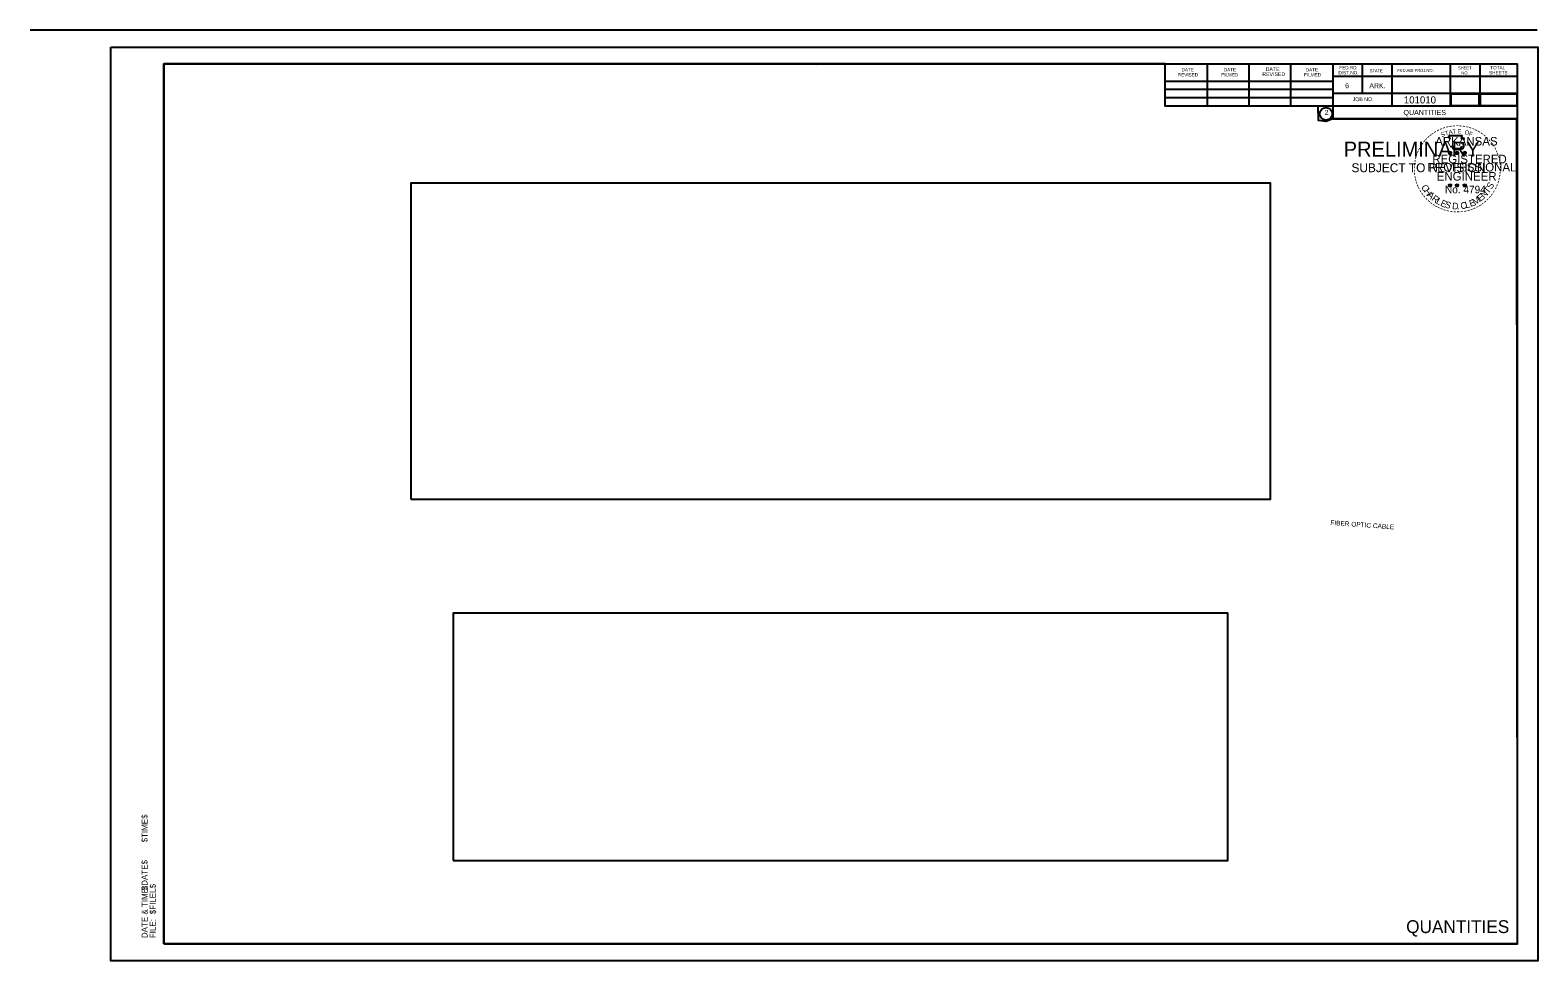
# Model space of a CAD drawing. Extents: x 9844 to 18514, y 8651 to 12569.
# Drawn here: x 9844 to 11605, y 9980 to 11067 of the extents above; entities that cross this region are included whole.
import ezdxf

# ---------------------------------------------------------------- set-up
doc = ezdxf.new("R2010")
doc.units = 0
for name, color, linetype in [('Default', 7, 'Continuous'), ('Quantities', 7, 'Continuous'), ('R_Border Notes', 7, 'Continuous'), ('R_No Plot', 7, 'Continuous'), ('S_FIBER_OPTIC_CABLE_ANNOT', 7, 'Continuous'), ('STAMP_PE_CRAFTON-SIGNATURE', 7, 'Continuous'), ('STAMP_PE_SEAL-INFO', 7, 'Continuous'), ('STAMP_PE_TXT', 7, 'Continuous'), ('STAMP_PRELIMINARY', 7, 'Continuous'), ('Total_Pages', 7, 'Continuous')]:
    doc.layers.add(name, color=color, linetype=linetype)

msp = doc.modelspace()

# ---------------------------------------------------------------- linework, layer by layer
at = {"layer": 'Quantities'}
for points in [[(10288.4, 10519), (11292.5, 10519), (11292.5, 10888.2), (10288.4, 10888.2)], [(10338.1, 10097.4), (11242.8, 10097.4), (11242.8, 10386), (10338.1, 10386)]]:
    msp.add_lwpolyline(points, close=True, dxfattribs=at)
at = {"layer": 'R_No Plot'}
msp.add_lwpolyline([(11502.9, 10978.6), (11536.2, 10978.6), (11536.2, 10991.9), (11502.9, 10991.9)], close=True, dxfattribs=at)
at = {"layer": 'STAMP_PE_SEAL-INFO'}
for points in [[(9938, 11046.8), (11604.7, 11046.8), (11604.7, 9980.1), (9938, 9980.1)], [(10000, 10000), (11580.9, 10000), (11580.3, 10963.3), (11365.4, 10963.3), (11357.3, 10959.9), (11348.5, 10961.4), (11348.3, 10977.9), (11169.6, 10977.9), (11169.6, 11027.3), (10000, 11027.3)], [(10000, 10000), (11580.9, 10000), (11580.3, 10963.3), (11365.4, 10963.3), (11357.3, 10959.9), (11348.5, 10961.4), (11348.3, 10977.9), (11169.6, 10977.9), (11169.6, 11027.3), (10000, 11027.3)], [(10000, 10000), (11580.9, 10000), (11580.3, 10963.3), (11365.4, 10963.3), (11357.3, 10959.9), (11348.5, 10961.4), (11348.3, 10977.9), (11169.6, 10977.9), (11169.6, 11027.3), (10000, 11027.3)]]:
    msp.add_lwpolyline(points, close=True, dxfattribs=at)
at = {"layer": 'STAMP_PE_TXT'}
for p, q in [((11500.3, 10924), (11502.1, 10923.5)), ((11500.3, 10924), (11501.6, 10923.8)), ((11500.3, 10924), (11501.5, 10923.4)), ((11501, 10922), (11502.1, 10923.5)), ((11501, 10922), (11501.6, 10923.2)), ((11501, 10922), (11502, 10923.1)), ((11502.1, 10925.3), (11501.8, 10924.1)), ((11503.1, 10922), (11502, 10923.1)), ((11502.1, 10923.5), (11502.1, 10925.3)), ((11502.1, 10925.3), (11502.3, 10924.1)), ((11503.8, 10924), (11502.1, 10923.5)), ((11503.1, 10922), (11502.1, 10923.5)), ((11503.8, 10924), (11502.4, 10923.8)), ((11503.1, 10922), (11502.4, 10923.5)), ((11503.8, 10924), (11502.8, 10923.5)), ((11508.7, 10924), (11510.4, 10923.5)), ((11508.7, 10924), (11509.9, 10923.8)), ((11508.7, 10924), (11509.8, 10923.4)), ((11509.3, 10922), (11510.4, 10923.5)), ((11509.3, 10922), (11510, 10923.2)), ((11509.3, 10922), (11510.4, 10923.1)), ((11510.4, 10925.3), (11510.2, 10924.1)), ((11510.4, 10923.5), (11510.4, 10925.3)), ((11510.4, 10925.3), (11510.6, 10924.1)), ((11512.1, 10924), (11510.4, 10923.5)), ((11511.5, 10922), (11510.4, 10923.5)), ((11511.5, 10922), (11510.4, 10923.1)), ((11512.1, 10924), (11510.7, 10923.8)), ((11511.5, 10922), (11510.8, 10923.5)), ((11512.1, 10924), (11511.1, 10923.5)), ((11517.5, 10924), (11519.2, 10923.4)), ((11517.5, 10924), (11518.7, 10923.8)), ((11517.5, 10924), (11518.7, 10923.4)), ((11518.1, 10921.9), (11519.2, 10923.4)), ((11518.1, 10921.9), (11518.8, 10923.2)), ((11518.1, 10921.9), (11519.2, 10923)), ((11519.2, 10925.3), (11519, 10924)), ((11519.2, 10923.4), (11519.2, 10925.3)), ((11519.2, 10925.3), (11519.5, 10924)), ((11521, 10924), (11519.2, 10923.4)), ((11520.3, 10921.9), (11519.2, 10923.4)), ((11520.3, 10921.9), (11519.2, 10923)), ((11521, 10924), (11519.5, 10923.7)), ((11520.3, 10921.9), (11519.6, 10923.4)), ((11521, 10924), (11519.9, 10923.5)), ((11500.3, 10886.2), (11502, 10885.6)), ((11500.3, 10886.2), (11501.6, 10886)), ((11500.3, 10886.2), (11501.5, 10885.6)), ((11501, 10884.1), (11502, 10885.6)), ((11501, 10884.1), (11501.6, 10885.4)), ((11501, 10884.1), (11502, 10885.2)), ((11502, 10887.4), (11501.8, 10886.2)), ((11502, 10885.6), (11502, 10887.4)), ((11502, 10887.4), (11502.3, 10886.2)), ((11503.8, 10886.2), (11502, 10885.6)), ((11503.1, 10884.1), (11502, 10885.6)), ((11503.1, 10884.1), (11502, 10885.2)), ((11503.8, 10886.2), (11502.3, 10885.9)), ((11503.1, 10884.1), (11502.4, 10885.6)), ((11503.8, 10886.2), (11502.7, 10885.7)), ((11508.6, 10886.2), (11510.4, 10885.6)), ((11508.6, 10886.2), (11509.9, 10886)), ((11508.6, 10886.2), (11509.8, 10885.6)), ((11509.3, 10884.1), (11510.4, 10885.6)), ((11509.3, 10884.1), (11509.9, 10885.4)), ((11509.3, 10884.1), (11510.4, 10885.2)), ((11510.4, 10887.4), (11510.2, 10886.2)), ((11510.4, 10885.6), (11510.4, 10887.4)), ((11510.4, 10887.4), (11510.6, 10886.2)), ((11512.1, 10886.2), (11510.4, 10885.6)), ((11511.4, 10884.1), (11510.4, 10885.6)), ((11511.4, 10884.1), (11510.4, 10885.2)), ((11512.1, 10886.2), (11510.7, 10885.9)), ((11511.4, 10884.1), (11510.8, 10885.6)), ((11512.1, 10886.2), (11511.1, 10885.7)), ((11517.5, 10886.1), (11519.2, 10885.6)), ((11517.5, 10886.1), (11518.7, 10885.9)), ((11517.5, 10886.1), (11518.7, 10885.5)), ((11518.1, 10884.1), (11519.2, 10885.6)), ((11518.1, 10884.1), (11518.8, 10885.3)), ((11518.1, 10884.1), (11519.2, 10885.2)), ((11519.2, 10887.4), (11519, 10886.1)), ((11519.2, 10885.6), (11519.2, 10887.4)), ((11519.2, 10887.4), (11519.5, 10886.1)), ((11520.9, 10886.1), (11519.2, 10885.6)), ((11520.3, 10884.1), (11519.2, 10885.6)), ((11520.3, 10884.1), (11519.2, 10885.2)), ((11520.9, 10886.1), (11519.5, 10885.9)), ((11520.3, 10884.1), (11519.6, 10885.5)), ((11520.9, 10886.1), (11519.9, 10885.6))]:
    msp.add_line(p, q, dxfattribs=at)
for points in [[(11500.5, 10943.4), (11501.9, 10939.3)], [(11518.1, 10938.8), (11518.8, 10940.2), (11515.4, 10940.1), (11516.1, 10943.4), (11500.5, 10943.4)], [(11502.1, 10925.3), (11503.1, 10922), (11500.3, 10924), (11503.8, 10924), (11501, 10922), (11502.1, 10925.3)], [(11503, 10931.3), (11503, 10930.9), (11505.8, 10930.8), (11505.5, 10928.4), (11514.9, 10928.4), (11515.9, 10931.1)], [(11510.4, 10925.3), (11511.5, 10922), (11508.7, 10924), (11512.1, 10924), (11509.3, 10922), (11510.4, 10925.3)], [(11519.2, 10925.3), (11520.3, 10921.9), (11517.5, 10924), (11521, 10924), (11518.1, 10921.9), (11519.2, 10925.3)], [(11502, 10887.4), (11503.1, 10884.1), (11500.3, 10886.2), (11503.8, 10886.2), (11501, 10884.1), (11502, 10887.4)], [(11510.4, 10887.4), (11511.4, 10884.1), (11508.6, 10886.2), (11512.1, 10886.2), (11509.3, 10884.1), (11510.4, 10887.4)], [(11519.2, 10887.4), (11520.3, 10884.1), (11517.5, 10886.1), (11520.9, 10886.1), (11518.1, 10884.1), (11519.2, 10887.4)]]:
    msp.add_lwpolyline(points, dxfattribs=at)
for centre, radius in [((11502, 10923.5), 0.861), ((11502, 10923.5), 0.723), ((11502, 10923.5), 0.579), ((11502, 10923.5), 0.495), ((11502, 10923.5), 0.374), ((11502, 10923.5), 0.248), ((11502, 10923.5), 0.148), ((11510.4, 10923.5), 0.861), ((11510.4, 10923.5), 0.723), ((11510.4, 10923.5), 0.579), ((11510.4, 10923.5), 0.495), ((11510.4, 10923.5), 0.374), ((11510.4, 10923.5), 0.248), ((11510.4, 10923.5), 0.148), ((11519.2, 10923.4), 0.861), ((11519.2, 10923.4), 0.723), ((11519.2, 10923.4), 0.579), ((11519.2, 10923.4), 0.495), ((11519.2, 10923.4), 0.374), ((11519.2, 10923.4), 0.248), ((11519.2, 10923.4), 0.148), ((11502, 10885.6), 0.861), ((11502, 10885.6), 0.723), ((11502, 10885.6), 0.579), ((11502, 10885.6), 0.495), ((11502, 10885.6), 0.374), ((11502, 10885.6), 0.248), ((11502, 10885.6), 0.148), ((11510.4, 10885.6), 0.861), ((11510.4, 10885.6), 0.723), ((11510.4, 10885.6), 0.579), ((11510.4, 10885.6), 0.495), ((11510.4, 10885.6), 0.374), ((11510.4, 10885.6), 0.248), ((11510.4, 10885.6), 0.148), ((11519.2, 10885.6), 0.861), ((11519.2, 10885.6), 0.723), ((11519.2, 10885.6), 0.579), ((11519.2, 10885.6), 0.495), ((11519.2, 10885.6), 0.374), ((11519.2, 10885.6), 0.248), ((11519.2, 10885.6), 0.148)]:
    msp.add_circle(centre, radius, dxfattribs=at)
at = {"layer": 'STAMP_PRELIMINARY'}
for p, q in [((11603.9, 11066.7), (9843.9, 11066.7)), ((10000, 11027.3), (11580.9, 11027.3)), ((10000, 10000), (10000, 11027.3)), ((10762.6, 11026), (10762.6, 11026)), ((10762.6, 11026), (10762.6, 11026)), ((11169.6, 10977.9), (11169.6, 11027.3)), ((11218.9, 10977.9), (11218.9, 11026.3)), ((11267.7, 10977.9), (11267.7, 11026.3)), ((11316.1, 10977.9), (11316.1, 11026.3)), ((11365.4, 11027.3), (11365.4, 10963.3)), ((11399.6, 11027.3), (11399.6, 10992.6)), ((11434.3, 11027.3), (11434.3, 10977.9)), ((11502.2, 11027.3), (11502.2, 10977.9)), ((11536.9, 11027.3), (11536.9, 10977.9)), ((11580.9, 10000), (11580.9, 11027.3)), ((11169.6, 11007.2), (11365.4, 11007.2)), ((11580.9, 11012.6), (11365.4, 11012.6)), ((11580.9, 11012.7), (11580.9, 11012.7)), ((11169.6, 10997.9), (11365.4, 10997.9)), ((11169.6, 10988.2), (11365.4, 10988.2)), ((11580.9, 10992.6), (11365.4, 10992.6)), ((11580.9, 10977.9), (11169.6, 10977.9)), ((11365.4, 10963.3), (11580.9, 10963.3)), ((11580.9, 10000), (10000, 10000))]:
    msp.add_line(p, q, dxfattribs=at)
msp.add_circle((11357.3, 10969), 7.33, dxfattribs=at)
at = {"layer": 'Total_Pages'}
msp.add_lwpolyline([(11537.4, 10978.6), (11580.4, 10978.6), (11580.4, 10991.9), (11537.4, 10991.9)], close=True, dxfattribs=at)

# ---------------------------------------------------------------- texts
at = {"layer": 'Default'}
for s, height, p in [('$TIME$', 6.98, (9981, 10118.4)), ('$DATE$', 6.98, (9981, 10062.5)), ('DATE & TIME:', 6.984, (9981, 10006.6)), ('$FILEL$', 6.98, (9990.6, 10034.5)), ('FILE: ', 6.98, (9990.6, 10006.6))]:
    msp.add_text(s, height=height, rotation=90, dxfattribs=at).set_placement(p)
at = {"layer": 'R_Border Notes'}
for s, height, p in [('101010', 8.4, (11448.2, 10981.1)), ('QUANTITIES', 6, (11447.7, 10967.6))]:
    msp.add_text(s, height=height, dxfattribs=at).set_placement(p)
at = {"layer": 'S_FIBER_OPTIC_CABLE_ANNOT'}
msp.add_text('FIBER OPTIC CABLE', height=5.5, rotation=356.029, dxfattribs=at).set_placement((11362.2, 10489))
at = {"layer": 'STAMP_PE_CRAFTON-SIGNATURE'}
for s, height, p in [('PRELIMINARY', 17.5, (11377.9, 10919)), ('SUBJECT TO REVISION', 10.376, (11387, 10900.9))]:
    msp.add_text(s, height=height, dxfattribs=at).set_placement(p)
at = {"layer": 'STAMP_PE_TXT'}
for s, height, rotation, p in [('-', 8, 24.3072, (11491.1, 10947.7)), ('-', 8, 19.1761, (11494.3, 10949.1)), ('-', 8, 13.6302, (11498, 10950.3)), ('-', 8, 10.2193, (11501.4, 10951.1)), ('-', 8, 5.8968, (11505, 10951.6)), ('-', 8, 0.1862, (11508.9, 10952)), ('-', 8, 357.743, (11512.5, 10951.9)), ('-', 8, 352.1617, (11516.2, 10951.6)), ('-', 8, 347.2049, (11519.8, 10951.1)), ('-', 8, 342.3362, (11523, 10950.3)), ('-', 8, 337.8551, (11526.7, 10949.2)), ('-', 8, 54.2325, (11471.2, 10930.7)), ('-', 8, 50.6142, (11473.2, 10933.5)), ('-', 8, 48.4231, (11475.3, 10935.9)), ('-', 8, 42.9622, (11477.5, 10938.3)), ('-', 8, 38.9507, (11479.7, 10940.4)), ('-', 8, 36.2317, (11482, 10942.3)), ('-', 8, 34.0636, (11484.9, 10944.3)), ('-', 8, 28.7918, (11487.9, 10946.1)), ('S', 5, 21.594, (11492.3, 10941.8)), ('T', 5, 16.4036, (11496.9, 10943.5)), ('A', 5, 11.2132, (11501, 10944.7)), ('T', 5, 6.0228, (11505.2, 10945.6)), ('E', 5, 0.8323, (11510.8, 10946.1)), ('O', 5, 350.4515, (11518.8, 10945.1)), ('F', 5, 340.0707, (11523.5, 10943.9)), ('-', 8, 334.1211, (11529.8, 10947.8)), ('-', 8, 329.6409, (11532.7, 10946.4)), ('-', 8, 325.8627, (11535.9, 10944.6)), ('-', 8, 320.5297, (11539, 10942.5)), ('-', 8, 315.5786, (11542, 10940)), ('-', 8, 309.8797, (11544.8, 10937.3)), ('-', 8, 306.6522, (11547.5, 10934.3)), ('-', 8, 75.461, (11464.6, 10915.2)), ('-', 8, 72.3945, (11465.6, 10918.8)), ('-', 8, 67.7743, (11466.7, 10921.9)), ('-', 8, 62.8713, (11468, 10925)), ('-', 8, 58.0706, (11469.6, 10928)), ('-', 7, 303.6753, (11549.9, 10931.4)), ('-', 8, 299.6684, (11551.5, 10928.4)), ('-', 8, 294.6628, (11553.1, 10925.3)), ('-', 8, 290.5728, (11554.4, 10922.5)), ('-', 8, 285.1233, (11555.6, 10919.6)), ('-', 8, 89.0622, (11463.4, 10904.7)), ('-', 8, 94.1959, (11463.6, 10901.1)), ('-', 8, 98.9479, (11464, 10897.7)), ('-', 8, 85.1863, (11463.6, 10908.2)), ('-', 8, 81.2013, (11464, 10911.6)), ('-', 8, 280.5493, (11556.6, 10915.9)), ('-', 8, 276.5962, (11557.4, 10912)), ('-', 8, 263.5172, (11557.7, 10901.9)), ('-', 8, 274.3301, (11557.7, 10908.4)), ('-', 8, 269.9407, (11557.8, 10905.2)), ('-', 8, 101.7149, (11464.7, 10894.1)), ('-', 8, 105.4578, (11465.5, 10891.1)), ('-', 8, 109.0874, (11466.5, 10887.9)), ('-', 8, 114.0643, (11467.8, 10884.9)), ('-', 8, 115.7289, (11469.3, 10881.9)), ('C', 7.7, 296.9133, (11468.2, 10883.9)), ('H', 7.7, 303.2799, (11471.1, 10878.7)), ('T', 7.7, 51.5114, (11546.8, 10875.1)), ('S', 7.7, 57.878, (11550.5, 10880.3)), ('-', 8, 244.6197, (11553.5, 10885.1)), ('-', 8, 247.8887, (11554.8, 10888.3)), ('-', 8, 255.7626, (11555.9, 10891.8)), ('-', 8, 255.7626, (11556.8, 10895.3)), ('-', 8, 260.9953, (11557.4, 10898.6)), ('-', 8, 120.4471, (11471.1, 10878.9)), ('-', 8, 125.8934, (11473.1, 10876.1)), ('-', 8, 130.7181, (11475.4, 10873.4)), ('-', 8, 134.2238, (11478, 10870.6)), ('A', 7.7, 316.013, (11474.8, 10873.6)), ('-', 8, 138.9338, (11480.7, 10868.3)), ('-', 8, 144.6463, (11483.4, 10866.3)), ('R', 7.7, 322.3796, (11479.9, 10868.7)), ('L', 7.7, 328.7461, (11485, 10864.9)), ('E', 7.7, 335.1127, (11490.1, 10862.1)), ('S', 7.7, 341.4792, (11495.4, 10860)), ('D', 7.7, 354.2124, (11504.2, 10857.9)), ('C', 7.7, 6.9455, (11514.7, 10857.7)), ('L', 7.7, 13.3121, (11520.6, 10858.7)), ('E', 7.7, 19.6786, (11526.1, 10860.3)), ('M', 7.7, 32.4117, (11531.2, 10862.1)), ('E', 7.7, 38.7783, (11537.6, 10866.2)), ('N', 7.7, 45.1449, (11542, 10869.9)), ('-', 8, 215.7363, (11539.6, 10867.6)), ('-', 8, 221.0851, (11542.4, 10869.9)), ('-', 8, 225.7653, (11545, 10872.5)), ('-', 8, 231.2538, (11547.4, 10875.3)), ('-', 8, 233.8452, (11549.5, 10878.1)), ('-', 8, 239.0712, (11551.5, 10881.4)), ('-', 8, 148.0898, (11486.2, 10864.4)), ('-', 8, 151.5704, (11489.1, 10862.8)), ('-', 8, 154.6002, (11491.7, 10861.6)), ('-', 8, 158.5612, (11494.9, 10860.3)), ('-', 8, 162.7983, (11498.3, 10859.2)), ('-', 8, 167.5555, (11501.9, 10858.4)), ('-', 8, 173.1155, (11505.7, 10857.9)), ('-', 8, 176.5183, (11509.5, 10857.6)), ('-', 8, 181.5918, (11513.2, 10857.7)), ('.', 7.7, 0.5789, (11510.1, 10857.5)), ('-', 8, 185.8167, (11517.2, 10858.1)), ('-', 8, 191.2858, (11520.9, 10858.7)), ('-', 8, 195.4743, (11524.6, 10859.7)), ('-', 8, 200.7184, (11528, 10860.9)), ('-', 8, 204.2516, (11531, 10862.3)), ('-', 8, 207.3568, (11534.2, 10863.9)), ('-', 8, 212.2491, (11537, 10865.6))]:
    msp.add_text(s, height=height, rotation=rotation, dxfattribs=at).set_placement(p)
for s, height, p in [('ARKANSAS', 10, (11484.8, 10932)), ('REGISTERED', 10, (11481.4, 10911.2)), ('PROFESSIONAL', 10, (11475.6, 10901.7)), ('ENGINEER', 10, (11486.6, 10891.1)), ('No. 4794', 8.78, (11496.2, 10876.3))]:
    msp.add_text(s, height=height, dxfattribs=at).set_placement(p)
at = {"layer": 'STAMP_PRELIMINARY'}
for s, height, p in [('DATE', 3.91, (11188.6, 11018.5)), ('DATE', 3.91, (11237.9, 11018.5)), ('DATE', 4.4, (11286.8, 11019)), ('DATE', 3.91, (11333.7, 11018.5)), ('FED.RD.', 3.91, (11372.8, 11020.9)), ('SHEET', 3.42, (11511.5, 11020.9)), ('TOTAL', 3.91, (11549.1, 11020.9)), ('REVISED', 3.91, (11184.2, 11012.6)), ('FILMED', 3.91, (11235, 11012.6)), ('REVISED', 4.4, (11282.9, 11013.1)), ('FILMED', 3.91, (11331.7, 11012.6)), ('DIST.NO.', 3.91, (11371.8, 11015)), ('6', 5.86, (11379.6, 10998.9)), ('STATE', 3.42, (11408.4, 11017.5)), ('FED.AID PROJ.NO.', 3.42, (11440.7, 11018)), ('NO.', 3.42, (11515.4, 11015)), ('SHEETS', 3.91, (11547.7, 11015)), ('JOB NO.', 4.4, (11388.4, 10983.8)), ('ARK.', 5.86, (11407.9, 10998.9)), ('2', 5.86, (11355.7, 10967.7)), ('QUANTITIES', 15, (11450.9, 10012.5))]:
    msp.add_text(s, height=height, dxfattribs=at).set_placement(p)

doc.saveas('drawing.dxf')
